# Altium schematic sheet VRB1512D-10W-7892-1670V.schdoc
size 277 x 190 mm; Device: default297x210; Symbol: default297x210; Name: default297x210; Size: "A4"; Id: /; File: EV_CMP7892_09B_01; Sheet: /; @Page No: 1; @Page Count: 1; @Schematic Name: VRB1512D-10W-7892-1670V; @Project Name: 反激隔离电源-VRB1512D-10W-7892-1670V; @Board Name: VRB1512D-10W-7892-1670V; @Update Date: 2025-07-02; @Create Time: 13:21:11; @Update Time: 10:01:37; @Page Name: VRB1512D-10W-7892-1670V; @Create Date: 2025-06-30
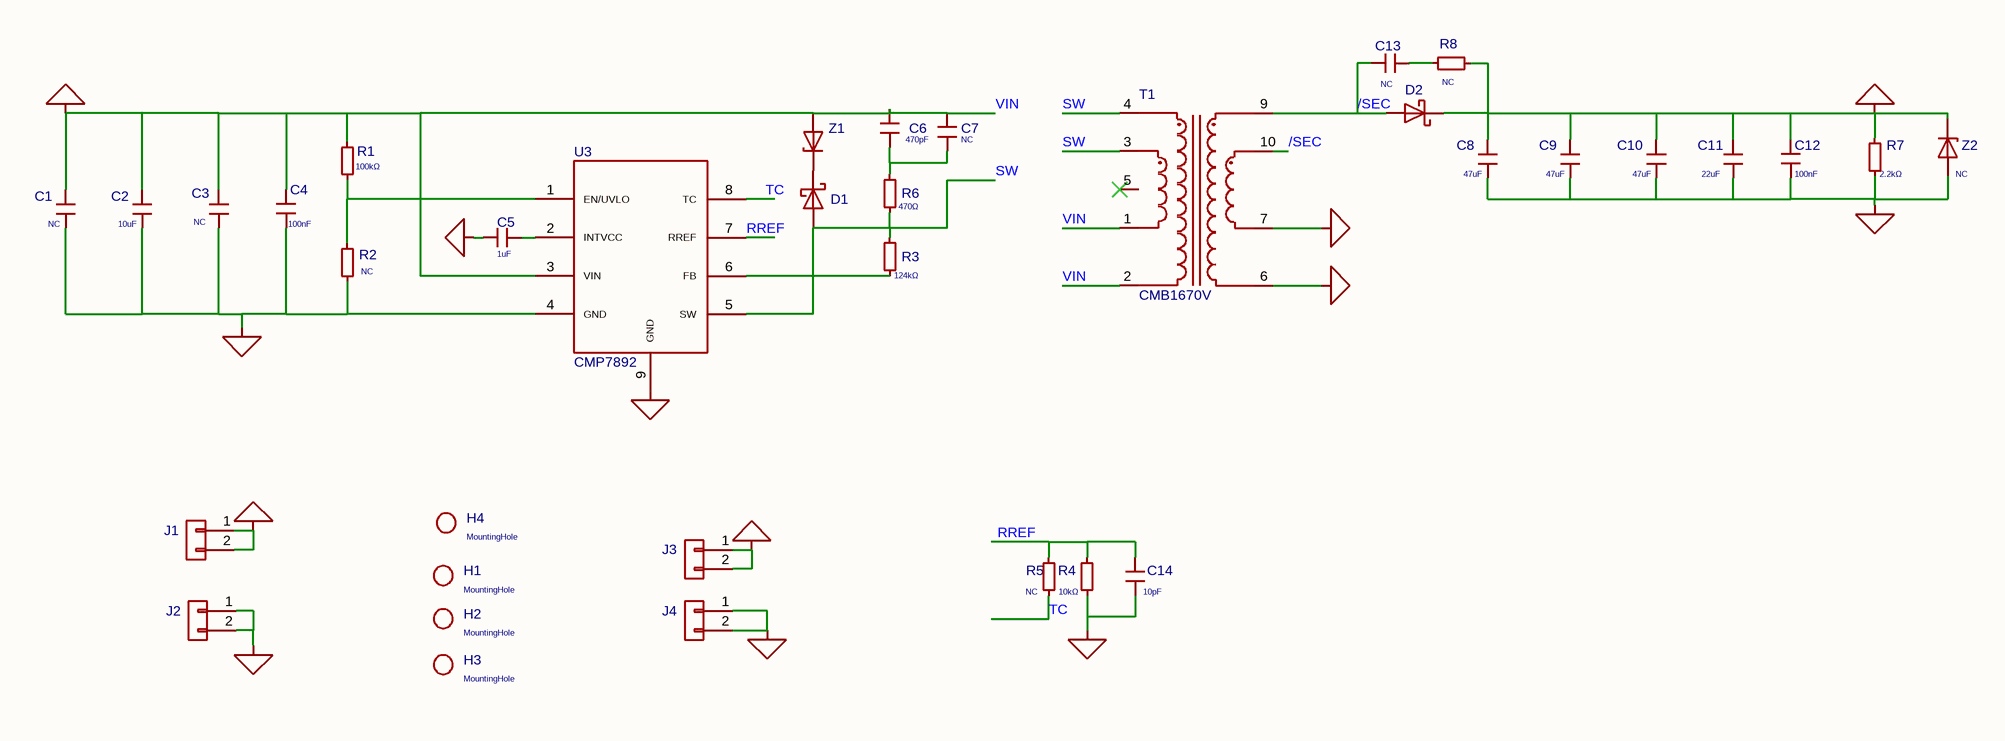
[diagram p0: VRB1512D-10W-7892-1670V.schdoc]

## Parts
C1  value NC  [MYLibrary:C1206]  (hidden comment: MY_C)
C2  10uF  [MYLibrary:C1206]
C3  value NC  [MYLibrary:C0805]  (hidden comment: MY_C)
C4  100nF  [MYLibrary:C0603]
C5  1uF  [MYLibrary:C0603]
C6  470pF  [MYLibrary:C0603]
C7  value NC  [MYLibrary:C0603]  (hidden comment: My_library_C)
C8  47uF  [MYLibrary:C1206]
C9  47uF  [MYLibrary:C1206]
C10  47uF  [MYLibrary:C1206]
C11  22uF  [MYLibrary:C0805]
C12  100nF  [MYLibrary:C0603]
C13  value NC  [MYLibrary:C0603]  (hidden comment: My_library_C)
C14  10pF  [MYLibrary:C0603]
D1  DSS210  [Diode_SMD:D_SOD-123]  (value not drawn)
D2  SSL510BF  [SMBF_L4.3-W3.6-LS5.3-RD]  (value not drawn)
H1  value MountingHole  [MountingHole:MountingHole_3.2mm_M3_DIN965]  (hidden comment: Mechanical_MountingHole)
H2  value MountingHole  [MountingHole:MountingHole_3.2mm_M3_DIN965]  (hidden comment: Mechanical_MountingHole)
H3  value MountingHole  [MountingHole:MountingHole_3.2mm_M3_DIN965]  (hidden comment: Mechanical_MountingHole)
H4  value MountingHole  [MountingHole:MountingHole_3.2mm_M3_DIN965]  (hidden comment: Mechanical_MountingHole)
J1  (no value)  [Connector_PinHeader_2.54mm:PinHeader_1x02_P2.54mm_Vertical]
J2  (no value)  [Connector_PinHeader_2.54mm:PinHeader_1x02_P2.54mm_Vertical]
J3  (no value)  [Connector_PinHeader_2.54mm:PinHeader_1x02_P2.54mm_Vertical]
J4  Connector_Generic_Conn_01x02  [Connector_PinHeader_2.54mm:PinHeader_1x02_P2.54mm_Vertical]  (value not drawn)
R1  100kΩ  [MYLibrary:R0603]
R2  value NC  [MYLibrary:R0603]  (hidden comment: Device_R_Small)
R3  124kΩ  [MYLibrary:R0603]
R4  10kΩ  [MYLibrary:R0603]
R5  value NC  [MYLibrary:R0603]  (hidden comment: Device_R_Small)
R6  470Ω  [MYLibrary:R1206]
R7  2.2kΩ  [MYLibrary:R0603]
R8  value NC  [MYLibrary:R0603]  (hidden comment: Device_R_Small)
T1  CMB1670V  [CMB1670V]
U3  CMP7892  [ESOP8]
Z1  1SMA5934A  [Diode_SMD:D_SMA]  (value not drawn)
Z2  value NC  [Diode_SMD:D_SMA]  (hidden comment: Diode_BZV55C75)

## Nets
GND1: C1.2 C2.2 C3.2 C4.1 C5.1 C14.1 J2.1(Pin_1) J2.2(Pin_2) R2.2 R4.2 U3.4(GND) U3.9(GND)
GND2: C8.2 C9.2 C10.2 C11.2 C12.1 J4.1(Pin_1) J4.2(Pin_2) R7.1 T1.6 T1.7 Z2.2(A)
VIN: C1.1 C2.1 C3.1 C4.2 C6.2 C7.2 J1.1(Pin_1) J1.2(Pin_2) R1.1 T1.1 T1.2 U3.3(VIN) Z1.2(A)
VOUT: C8.1 C9.1 C10.1 C11.1 C12.2 D2.1(K) J3.1(Pin_1) J3.2(Pin_2) R7.2 R8.1 Z2.1(K)
/SEC: C13.2 D2.2(A) T1.9 T1.10
RREF: C14.2 R4.1 R5.2 U3.7(RREF)
SW: D1.2(A) R3.2 R6.1 T1.3 T1.4 U3.5(SW)
TC: R5.1 U3.8(TC)
NetC5_2: C5.2 U3.2(INTVCC)
NetC6_1: C6.1 C7.1 R6.2
NetC13_1: C13.1 R8.2
NetD1_1: D1.1(K) Z1.1(K)
NetR1_2: R1.2 R2.1 U3.1(EN/UVLO)
NetR3_1: R3.1 U3.6(FB)

Not connected (* = marked no-connect by the designer): T1 5*

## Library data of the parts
C1 = MY_C: GRM31CR61H106KA12L; Users: REF**; ki_fp_filters: C_*; AddInBom: yes
C2 = CC1206KKX5R9BB106: 容值:10uF;精度:±10%;额定电压:50V;材质(温度系数):X5R;; Manufacturer: YAGEO(国巨); Symbol: MY_C; AddInBom: yes; ModelId: e4be705b945545a48e666415e3682bd8; ModelName: C1206_L3.2-W1.6-H1.3; ModelTransform: 125.984,62.992,0,0,0,0,0,0,0; Tolerance: ±10%; Voltage Rated: 50V; Temperature Coefficient: X5R
C3 = MY_C: 0805; Users: REF**; ki_fp_filters: C_*; AddInBom: yes
C4 C12 = CC0603KRX7R9BB104: 容值:100nF;精度:±10%;额定电压:50V;温度系数:X7R;; Manufacturer: YAGEO(国巨); Symbol: MY_C; Voltage Rating: 50V; AddInBom: yes; ModelId: ac125912035d415993ca9572d50418b1; ModelName: C0603_L1.6-W0.8-H0.8; ModelTransform: 62.992,31.496,0,0,0,0,0,0,0; Tolerance: ±10%; Temperature Coefficient: X7R
C5 = CC0603KRX7R9BB105: 容值:1uF;精度:±10%;额定电压:50V;材质(温度系数):X7R;; Manufacturer: YAGEO(国巨); Symbol: MY_C; AddInBom: yes; ModelId: ac125912035d415993ca9572d50418b1; ModelName: C0603_L1.6-W0.8-H0.8; ModelTransform: 62.992,31.496,0,0,0,0,0,0,0; Tolerance: ±10%; Voltage Rated: 50V; Temperature Coefficient: X7R
C6 = CC0603KRX7R9BB471: 容值:470pF;精度:±10%;额定电压:50V;材质(温度系数):X7R;; Manufacturer: YAGEO(国巨); Symbol: My_library_C; AddInBom: yes; ModelId: ac125912035d415993ca9572d50418b1; ModelName: C0603_L1.6-W0.8-H0.8; ModelTransform: 62.992,31.496,0,0,0,0,0,0,0; Tolerance: ±10%; Voltage Rated: 50V; Temperature Coefficient: X7R
C7 C13 = My_library_C: AddInBom: yes
C8-C10 = C3216X5R1E476MTJ00E: 容值:47uF;精度:±20%;额定电压:25V;温度系数:X5R;; Manufacturer: TDK; Symbol: MY_C; AddInBom: yes; ModelId: e4be705b945545a48e666415e3682bd8; ModelName: C1206_L3.2-W1.6-H1.3; ModelTransform: 125.984,62.992,0,0,0,0,0,0,0; Tolerance: ±20%; Voltage Rating: 25V; Temperature Coefficient: X5R
C11 = CL21A226MAQNNNE: 容值:22uF;精度:±20%;额定电压:25V;温度系数:X5R;; Manufacturer: SAMSUNG(三星); Symbol: MY_C; AddInBom: yes; ModelId: 1ba041120af144c991958decab20d241; ModelName: C0805_L2.0-W1.3-H1.3; ModelTransform: 78.74,51.181,0,0,0,0,0,0.0005,0; Tolerance: ±20%; Voltage Rating: 25V; Temperature Coefficient: X5R
C14 = CC0603JRNPO9BN100: 容值:10pF;精度:±5%;额定电压:50V;材质(温度系数):NP0;; Manufacturer: YAGEO(国巨); Symbol: My_library_C; AddInBom: yes; ModelId: ac125912035d415993ca9572d50418b1; ModelName: C0603_L1.6-W0.8-H0.8; ModelTransform: 62.992,31.496,0,0,0,0,0,0,0; Tolerance: ±5%; Voltage Rated: 50V; Temperature Coefficient: NP0
D1 = DSS210: 二极管配置:独立式;正向压降(Vf):850mV@2A;直流反向耐压(Vr):100V;整流电流:2A;; Manufacturer: CJ(江苏长电/长晶); Symbol: My library_DSS210; AddInBom: yes; ModelId: 125b22121bda4d3999c0a2016797619b; ModelName: SOD-123_L2.8-W1.8-H1.4-LS3.7; ModelTransform: 145.669,70.866,0,0,0,0,0,0,0; Diode Configuration: 独立式; Reverse Voltage (Vr): 100V; Rectified Current: 2A; Reverse Leakage Current (Ir): 100uA@100V
D2 = SSL510BF: 正向压降(Vf):600mV@5A;直流反向耐压(Vr):100V;整流电流:5A;; Manufacturer: 晶导微电子; Symbol: My library_DSS210; AddInBom: yes; ModelId: e588e20330de467e9d3d3ec1dc43b1a6; ModelTransform: 208.661,141.732,0,0,0,0,0,0,0; Voltage - DC Reverse(Vr): 100V; Current - Rectified: 5A; Reverse Leakage Current (Ir): 1mA@100V
H1-H4 = Mechanical_MountingHole: Users: REF**; ki_fp_filters: MountingHole*; AddInBom: yes
J1 J2 = conn_01x02: Symbol: Connector_Generic_Conn_01x02; AddInBom: yes
J3 = Connector_Generic_Conn_01x02: AddInBom: yes
J4 = Connector_Generic_Conn_01x02: Users: REF**; ki_fp_filters: Connector*:*_1x??_*; AddInBom: yes
R1 = RC0603FR-07100KL: 电阻类型:厚膜电阻;阻值:100kΩ;精度:±1%;功率:100mW;最大工作电压:75V;温度系数:±100ppm/℃;; Manufacturer: YAGEO(国巨); Symbol: Device_R_Small; AddInBom: yes; ModelId: fc143cca1e79419f9cd78b61e9279f08; ModelName: R0603; ModelTransform: 31.8897,63.7794,0,90,0,0,0,0,0; Tolerance: ±1%; Power(Watts): 100mW; Overload Voltage (Max): 75V
R2 R5 R8 = Device_R_Small: Resistor, small symbol; Users: REF**; ki_fp_filters: R_*; AddInBom: yes
R3 = RC0603FR-07124KL: 电阻类型:厚膜电阻;阻值:124kΩ;精度:±1%;功率:100mW;最大工作电压:75V;温度系数:±100ppm/℃;; Manufacturer: YAGEO(国巨); Symbol: Device_R_Small; AddInBom: yes; ModelId: fc143cca1e79419f9cd78b61e9279f08; ModelName: R0603; ModelTransform: 31.8897,63.7794,0,90,0,0,0,0,0; Tolerance: ±1%; Power(Watts): 100mW; Overload Voltage (Max): 75V
R4 = RC0603FR-0710KL: 电阻类型:厚膜电阻;阻值:10kΩ;精度:±1%;功率:100mW;最大工作电压:75V;温度系数:±100ppm/℃;; Manufacturer: YAGEO(国巨); Symbol: Device_R_Small; AddInBom: yes; ModelId: fc143cca1e79419f9cd78b61e9279f08; ModelName: R0603; ModelTransform: 31.8897,63.7794,0,90,0,0,0,0,0; Tolerance: ±1%; Power(Watts): 100mW; Overload Voltage (Max): 75V
R6 = RC1206FR-07470RL: 电阻类型:厚膜电阻;阻值:470Ω;精度:±1%;功率:250mW;最大工作电压:200V;温度系数:±100ppm/℃;; Manufacturer: YAGEO(国巨); Symbol: Device_R_Small; AddInBom: yes; ModelId: 89a1f13db2384da588040e0b3c55bf66; ModelName: R1206_L3.2-W1.6-H0.6; ModelTransform: 125.984,62.992,0,0,0,0,0,0,0; Tolerance: ±1%; Power(Watts): 250mW; Overload Voltage (Max): 200V
R7 = RC0603FR-072K2L: 电阻类型:厚膜电阻;阻值:2.2kΩ;精度:±1%;功率:100mW;工作电压:75V;温度系数:±100ppm/℃;; Manufacturer: YAGEO(国巨); Symbol: Device_R_Small; AddInBom: yes; ModelId: fc143cca1e79419f9cd78b61e9279f08; ModelName: R0603; ModelTransform: 31.8897,63.7794,0,90,0,0,0,0,0; Tolerance: ±1%; Power(Watts): 100mW; Voltage-Supply(Max): 75V
T1 = CMB1670V: Manufacturer: coileasy(线易); AddInBom: yes
U3 = CMP7892: AddInBom: yes; ModelId: f021853bf58e4dc7a473d26afc5d80ba0819f05c4eef4c71ace90d822a990e87; ModelName: ESOP-8_L4.9-W3.9-P1.27-LS6.0-BR-EP3.3; ModelTransform: 192.91300375461577,236.21999999999997,61.02350046932697,0,0,0,0,0,0
Z1 = 1SMA5934A: 二极管配置:独立式;稳压值(标称值):24V;稳压值(范围):21.6V~26.4V;耗散功率(Pd):1.5W;; Manufacturer: LGE(鲁光); 3D Model: 21b4297b05f34eb58397f8f5cb4541ec; Symbol: Diode_BZV55C75; AddInBom: yes; ModelName: SMA_L4.4-W2.6-LS5.1-RD; ModelTransform: 200.787,102.362,0,0,0,0,0,0,0; Diode Configuration: 独立式; Zener Voltage(Nom): 24V; Reverse Leakage Current (Ir): 1uA; Pd - Power Dissipation: 1.5W; Impedance(Zzt): 19Ω; Impedance(Zzk): 700Ω; Operating Junction Temperature Range: -55℃~+150℃
Z2 = Diode_BZV55C75: Users: REF**; ki_fp_filters: D*MiniMELF*; AddInBom: yes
